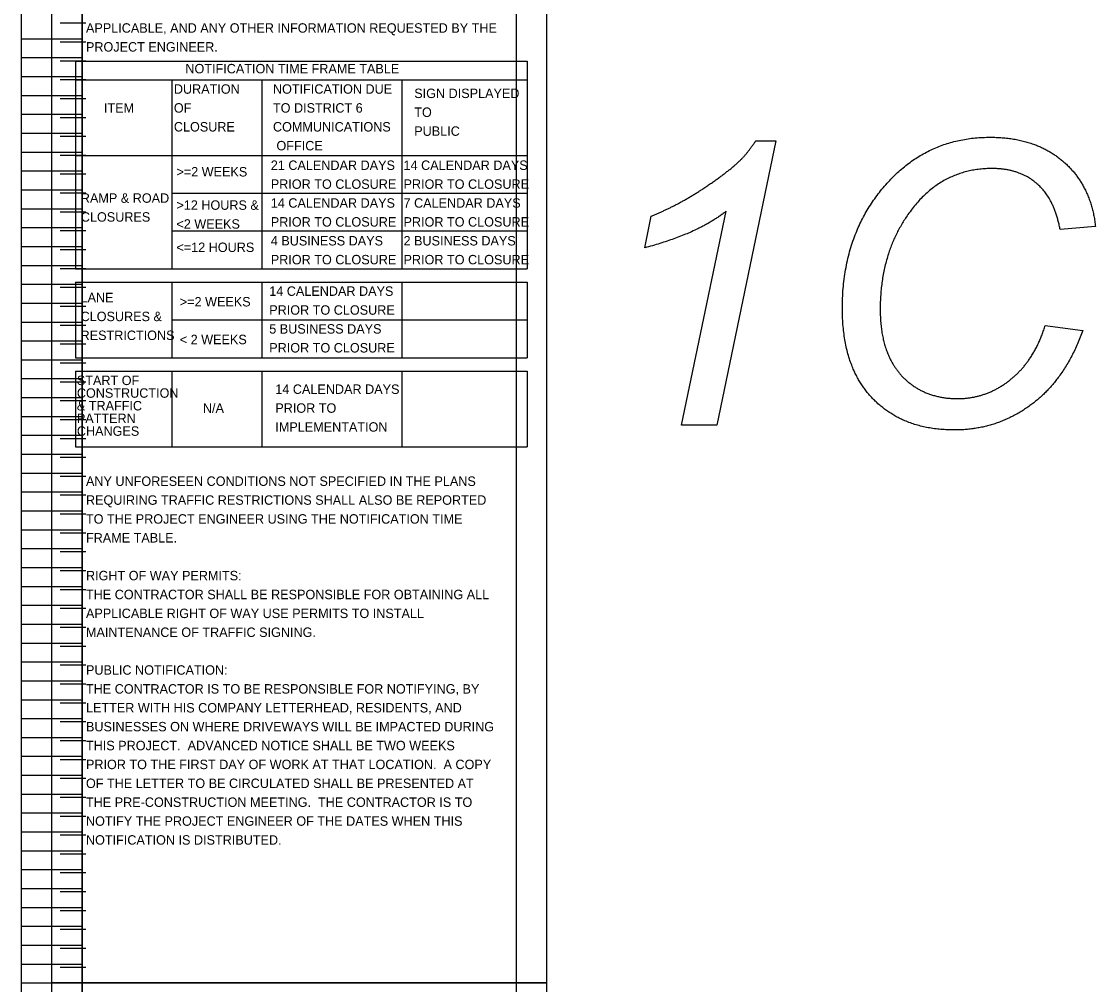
# Model space of a CAD drawing. Extents: x 12522 to 12538, y 1124 to 1850.
# Drawn here: x 12521.92 to 12537.85, y 1789.29 to 1803.57 of the extents above; entities that cross this region are included whole.
import ezdxf

# ---------------------------------------------------------------- set-up
doc = ezdxf.new("R2010")
doc.units = 0
doc.layers.add('SC_Scratch1', color=7, linetype='Continuous')
doc.layers.add('SH_Text', color=7, linetype='Continuous')

msp = doc.modelspace()

# ---------------------------------------------------------------- linework, layer by layer
at = {"layer": 'SC_Scratch1'}
for p, q in [((12521.919, 1789.311), (12521.919, 1809.471)), ((12522.819, 1789.311), (12522.819, 1809.471)), ((12522.819, 1789.311), (12522.819, 1809.471)), ((12522.819, 1809.471), (12522.819, 1789.311)), ((12529.259, 1809.471), (12529.259, 1789.311)), ((12522.876, 1803.541), (12522.492, 1803.541)), ((12521.919, 1803.311), (12522.819, 1803.311)), ((12522.876, 1803.261), (12522.492, 1803.261)), ((12521.919, 1803.031), (12522.819, 1803.031)), ((12522.876, 1802.981), (12522.492, 1802.981)), ((12521.919, 1802.751), (12522.819, 1802.751)), ((12522.876, 1802.701), (12522.492, 1802.701)), ((12521.919, 1802.471), (12522.819, 1802.471)), ((12522.876, 1802.421), (12522.492, 1802.421)), ((12521.919, 1802.191), (12522.819, 1802.191)), ((12522.876, 1802.141), (12522.492, 1802.141)), ((12521.919, 1801.911), (12522.819, 1801.911)), ((12522.876, 1801.861), (12522.492, 1801.861)), ((12521.919, 1801.631), (12522.819, 1801.631)), ((12522.876, 1801.581), (12522.492, 1801.581)), ((12521.919, 1801.351), (12522.819, 1801.351)), ((12522.876, 1801.301), (12522.492, 1801.301)), ((12521.919, 1801.071), (12522.819, 1801.071)), ((12522.876, 1801.021), (12522.492, 1801.021)), ((12521.919, 1800.791), (12522.819, 1800.791)), ((12522.876, 1800.741), (12522.492, 1800.741)), ((12531.166, 1800.212), (12531.263, 1800.683)), ((12521.919, 1800.511), (12522.819, 1800.511)), ((12522.876, 1800.461), (12522.492, 1800.461)), ((12537.852, 1800.529), (12537.327, 1800.481)), ((12521.919, 1800.231), (12522.819, 1800.231)), ((12522.876, 1800.181), (12522.492, 1800.181)), ((12521.919, 1799.951), (12522.819, 1799.951)), ((12522.876, 1799.901), (12522.492, 1799.901)), ((12521.919, 1799.671), (12522.819, 1799.671)), ((12522.876, 1799.621), (12522.492, 1799.621)), ((12521.919, 1799.391), (12522.819, 1799.391)), ((12522.876, 1799.341), (12522.492, 1799.341)), ((12521.919, 1799.111), (12522.819, 1799.111)), ((12522.876, 1799.061), (12522.492, 1799.061)), ((12537.107, 1799.06), (12537.664, 1798.983)), ((12521.919, 1798.831), (12522.819, 1798.831)), ((12522.876, 1798.781), (12522.492, 1798.781)), ((12521.919, 1798.551), (12522.819, 1798.551)), ((12522.876, 1798.501), (12522.492, 1798.501)), ((12521.919, 1798.271), (12522.819, 1798.271)), ((12522.876, 1798.221), (12522.492, 1798.221)), ((12521.919, 1797.991), (12522.819, 1797.991)), ((12522.876, 1797.941), (12522.492, 1797.941)), ((12521.919, 1797.711), (12522.819, 1797.711)), ((12522.876, 1797.661), (12522.492, 1797.661)), ((12521.919, 1797.431), (12522.819, 1797.431)), ((12522.876, 1797.381), (12522.492, 1797.381)), ((12521.919, 1797.151), (12522.819, 1797.151)), ((12522.876, 1797.101), (12522.492, 1797.101)), ((12521.919, 1796.871), (12522.819, 1796.871)), ((12522.876, 1796.821), (12522.492, 1796.821)), ((12521.919, 1796.591), (12522.819, 1796.591)), ((12522.876, 1796.541), (12522.492, 1796.541)), ((12521.919, 1796.311), (12522.819, 1796.311)), ((12522.876, 1796.261), (12522.492, 1796.261)), ((12521.919, 1796.031), (12522.819, 1796.031)), ((12522.876, 1795.981), (12522.492, 1795.981)), ((12521.919, 1795.751), (12522.819, 1795.751)), ((12522.876, 1795.701), (12522.492, 1795.701)), ((12521.919, 1795.471), (12522.819, 1795.471)), ((12522.876, 1795.421), (12522.492, 1795.421)), ((12521.919, 1795.191), (12522.819, 1795.191)), ((12522.876, 1795.141), (12522.492, 1795.141)), ((12521.919, 1794.911), (12522.819, 1794.911)), ((12522.876, 1794.861), (12522.492, 1794.861)), ((12521.919, 1794.631), (12522.819, 1794.631)), ((12522.876, 1794.581), (12522.492, 1794.581)), ((12521.919, 1794.351), (12522.819, 1794.351)), ((12522.876, 1794.301), (12522.492, 1794.301)), ((12521.919, 1794.071), (12522.819, 1794.071)), ((12522.876, 1794.021), (12522.492, 1794.021)), ((12521.919, 1793.791), (12522.819, 1793.791)), ((12522.876, 1793.741), (12522.492, 1793.741)), ((12521.919, 1793.511), (12522.819, 1793.511)), ((12522.876, 1793.461), (12522.492, 1793.461)), ((12521.919, 1793.231), (12522.819, 1793.231)), ((12522.876, 1793.181), (12522.492, 1793.181)), ((12521.919, 1792.951), (12522.819, 1792.951)), ((12522.876, 1792.901), (12522.492, 1792.901)), ((12521.919, 1792.671), (12522.819, 1792.671)), ((12522.876, 1792.621), (12522.492, 1792.621)), ((12521.919, 1792.391), (12522.819, 1792.391)), ((12522.876, 1792.341), (12522.492, 1792.341)), ((12521.919, 1792.111), (12522.819, 1792.111)), ((12522.876, 1792.061), (12522.492, 1792.061)), ((12521.919, 1791.831), (12522.819, 1791.831)), ((12522.876, 1791.781), (12522.492, 1791.781)), ((12521.919, 1791.551), (12522.819, 1791.551)), ((12522.876, 1791.501), (12522.492, 1791.501)), ((12521.919, 1791.271), (12522.819, 1791.271)), ((12522.876, 1791.221), (12522.492, 1791.221)), ((12521.919, 1790.991), (12522.819, 1790.991)), ((12522.876, 1790.941), (12522.492, 1790.941)), ((12521.919, 1790.711), (12522.819, 1790.711)), ((12522.876, 1790.661), (12522.492, 1790.661)), ((12521.919, 1790.431), (12522.819, 1790.431)), ((12522.876, 1790.381), (12522.492, 1790.381)), ((12521.919, 1790.151), (12522.819, 1790.151)), ((12522.876, 1790.101), (12522.492, 1790.101)), ((12521.919, 1789.871), (12522.819, 1789.871)), ((12522.876, 1789.821), (12522.492, 1789.821)), ((12521.919, 1789.591), (12522.819, 1789.591)), ((12522.876, 1789.541), (12522.492, 1789.541)), ((12521.919, 1789.311), (12522.819, 1789.311)), ((12521.919, 1769.151), (12521.919, 1789.311)), ((12521.919, 1789.311), (12522.819, 1789.311)), ((12522.819, 1769.151), (12522.819, 1789.311)), ((12529.259, 1789.311), (12522.819, 1789.311)), ((12522.819, 1789.311), (12522.819, 1769.151))]:
    msp.add_line(p, q, dxfattribs=at)
for points in [[(12522.369, 1809.471), (12529.709, 1809.471), (12529.709, 1789.311), (12522.369, 1789.311)], [(12522.369, 1789.311), (12529.709, 1789.311), (12529.709, 1769.151), (12522.369, 1769.151)], [(12522.819, 1789.311), (12529.259, 1789.311), (12529.259, 1769.151), (12522.819, 1769.151)]]:
    msp.add_lwpolyline(points, close=True, dxfattribs=at)
msp.add_lwpolyline([(12532.811, 1801.797), (12533.111, 1801.797), (12532.234, 1797.581), (12531.712, 1797.581), (12532.375, 1800.754)], dxfattribs=at)
for points in [[(12532.593, 1801.52), (12532.707, 1801.634), (12532.811, 1801.797)], [(12534.78, 1801.19), (12535.387, 1801.851), (12536.29, 1801.851)], [(12536.29, 1801.851), (12536.958, 1801.851), (12537.372, 1801.493)], [(12532.027, 1801.086), (12532.404, 1801.334), (12532.593, 1801.52)], [(12536.316, 1801.387), (12535.545, 1801.387), (12535.069, 1800.703)], [(12536.984, 1801.162), (12536.725, 1801.387), (12536.316, 1801.387)], [(12537.372, 1801.493), (12537.786, 1801.134), (12537.852, 1800.529)], [(12531.263, 1800.683), (12531.65, 1800.837), (12532.027, 1801.086)], [(12534.097, 1799.314), (12534.097, 1800.448), (12534.78, 1801.19)], [(12537.327, 1800.481), (12537.244, 1800.937), (12536.984, 1801.162)], [(12532.375, 1800.754), (12531.945, 1800.416), (12531.166, 1800.212)], [(12535.069, 1800.703), (12534.658, 1800.113), (12534.658, 1799.303)], [(12534.546, 1797.977), (12534.097, 1798.444), (12534.097, 1799.314)], [(12534.658, 1799.303), (12534.658, 1798.656), (12534.976, 1798.315)], [(12536.593, 1798.258), (12536.946, 1798.542), (12537.107, 1799.06)], [(12537.664, 1798.983), (12537.4, 1798.255), (12536.895, 1797.883)], [(12534.976, 1798.315), (12535.294, 1797.975), (12535.805, 1797.975)], [(12535.805, 1797.975), (12536.24, 1797.975), (12536.593, 1798.258)], [(12535.761, 1797.51), (12534.995, 1797.51), (12534.546, 1797.977)], [(12536.895, 1797.883), (12536.39, 1797.51), (12535.761, 1797.51)]]:
    msp.add_open_spline(points, degree=2, dxfattribs=at)
at = {"layer": 'SH_Text'}
for p, q in [((12522.719, 1802.981), (12529.423, 1802.981)), ((12522.719, 1802.981), (12522.719, 1799.901)), ((12529.423, 1802.981), (12529.423, 1799.901)), ((12522.719, 1802.701), (12529.423, 1802.701)), ((12524.152, 1802.701), (12524.152, 1799.901)), ((12525.486, 1802.701), (12525.486, 1799.901)), ((12527.561, 1802.701), (12527.561, 1799.901)), ((12522.719, 1801.581), (12529.423, 1801.581)), ((12524.152, 1801.021), (12529.423, 1801.021)), ((12524.152, 1800.461), (12529.423, 1800.461)), ((12522.719, 1799.901), (12529.423, 1799.901)), ((12522.719, 1799.701), (12529.423, 1799.701)), ((12522.719, 1799.701), (12522.719, 1798.581)), ((12524.152, 1799.701), (12524.152, 1798.581)), ((12525.486, 1799.701), (12525.486, 1798.581)), ((12527.561, 1799.701), (12527.561, 1798.581)), ((12529.423, 1799.701), (12529.423, 1798.581)), ((12524.152, 1799.141), (12529.423, 1799.141)), ((12522.719, 1798.581), (12529.423, 1798.581)), ((12522.719, 1798.381), (12529.423, 1798.381)), ((12522.719, 1798.381), (12522.719, 1797.261)), ((12524.152, 1798.381), (12524.152, 1797.261)), ((12525.486, 1798.381), (12525.486, 1797.261)), ((12527.561, 1798.381), (12527.561, 1797.261)), ((12529.423, 1798.381), (12529.423, 1797.261)), ((12522.719, 1797.261), (12529.423, 1797.261))]:
    msp.add_line(p, q, dxfattribs=at)

# ---------------------------------------------------------------- texts
for s, p in [('APPLICABLE, AND ANY OTHER INFORMATION REQUESTED BY THE ', (12522.876, 1803.401)), ('PROJECT ENGINEER.', (12522.876, 1803.121)), ('NOTIFICATION TIME FRAME TABLE', (12524.351, 1802.798)), ('DURATION', (12524.18, 1802.496)), ('NOTIFICATION DUE', (12525.65, 1802.496)), ('SIGN DISPLAYED', (12527.746, 1802.432)), ('ITEM', (12523.143, 1802.216)), ('OF', (12524.18, 1802.216)), ('TO DISTRICT 6', (12525.65, 1802.216)), ('TO', (12527.746, 1802.152)), ('CLOSURE', (12524.18, 1801.936)), ('COMMUNICATIONS', (12525.65, 1801.936)), ('PUBLIC', (12527.746, 1801.872)), (' OFFICE', (12525.65, 1801.656)), ('>=2 WEEKS', (12524.218, 1801.269)), ('21 CALENDAR DAYS', (12525.618, 1801.366)), ('14 CALENDAR DAYS', (12527.587, 1801.366)), ('PRIOR TO CLOSURE', (12525.618, 1801.086)), ('PRIOR TO CLOSURE', (12527.587, 1801.086)), ('RAMP & ROAD', (12522.8, 1800.879)), ('>12 HOURS &', (12524.218, 1800.775)), ('14 CALENDAR DAYS', (12525.618, 1800.806)), ('7 CALENDAR DAYS', (12527.587, 1800.806)), ('CLOSURES', (12522.8, 1800.599)), ('<2 WEEKS', (12524.218, 1800.495)), ('PRIOR TO CLOSURE', (12525.618, 1800.526)), ('PRIOR TO CLOSURE', (12527.587, 1800.526)), ('<=12 HOURS', (12524.218, 1800.149)), ('4 BUSINESS DAYS', (12525.618, 1800.246)), ('2 BUSINESS DAYS', (12527.587, 1800.246)), ('PRIOR TO CLOSURE', (12525.618, 1799.966)), ('PRIOR TO CLOSURE', (12527.587, 1799.966)), ('14 CALENDAR DAYS', (12525.595, 1799.499)), ('LANE', (12522.796, 1799.404)), ('>=2 WEEKS', (12524.268, 1799.342)), ('PRIOR TO CLOSURE', (12525.595, 1799.219)), ('CLOSURES &', (12522.796, 1799.124)), ('5 BUSINESS DAYS', (12525.595, 1798.939)), ('RESTRICTIONS', (12522.796, 1798.844)), ('< 2 WEEKS', (12524.268, 1798.782)), ('PRIOR TO CLOSURE', (12525.595, 1798.659)), ('START OF', (12522.741, 1798.176)), ('CONSTRUCTION', (12522.741, 1797.988)), ('14 CALENDAR DAYS', (12525.685, 1798.045)), ('& TRAFFIC', (12522.741, 1797.8)), ('N/A', (12524.611, 1797.764)), ('PRIOR TO', (12525.685, 1797.765)), ('PATTERN', (12522.741, 1797.612)), ('CHANGES', (12522.741, 1797.424)), ('IMPLEMENTATION', (12525.685, 1797.485)), ('ANY UNFORESEEN CONDITIONS NOT SPECIFIED IN THE PLANS ', (12522.876, 1796.681)), ('REQUIRING TRAFFIC RESTRICTIONS SHALL ALSO BE REPORTED ', (12522.876, 1796.401)), ('TO THE PROJECT ENGINEER USING THE NOTIFICATION TIME ', (12522.876, 1796.121)), ('FRAME TABLE. ', (12522.876, 1795.841)), ('RIGHT OF WAY PERMITS:', (12522.876, 1795.281)), ('THE CONTRACTOR SHALL BE RESPONSIBLE FOR OBTAINING ALL ', (12522.876, 1795.001)), ('APPLICABLE RIGHT OF WAY USE PERMITS TO INSTALL ', (12522.876, 1794.721)), ('MAINTENANCE OF TRAFFIC SIGNING.', (12522.876, 1794.441)), ('PUBLIC NOTIFICATION:', (12522.876, 1793.881)), ('THE CONTRACTOR IS TO BE RESPONSIBLE FOR NOTIFYING, BY ', (12522.876, 1793.601)), ('LETTER WITH HIS COMPANY LETTERHEAD, RESIDENTS, AND ', (12522.876, 1793.321)), ('BUSINESSES ON WHERE DRIVEWAYS WILL BE IMPACTED DURING ', (12522.876, 1793.041)), ('THIS PROJECT.  ADVANCED NOTICE SHALL BE TWO WEEKS ', (12522.876, 1792.761)), ('PRIOR TO THE FIRST DAY OF WORK AT THAT LOCATION.  A COPY ', (12522.876, 1792.481)), ('OF THE LETTER TO BE CIRCULATED SHALL BE PRESENTED AT ', (12522.876, 1792.201)), ('THE PRE-CONSTRUCTION MEETING.  THE CONTRACTOR IS TO ', (12522.876, 1791.921)), ('NOTIFY THE PROJECT ENGINEER OF THE DATES WHEN THIS ', (12522.876, 1791.641)), ('NOTIFICATION IS DISTRIBUTED.', (12522.876, 1791.361))]:
    msp.add_text(s, height=0.14, dxfattribs=at).set_placement(p)

doc.saveas('drawing.dxf')
